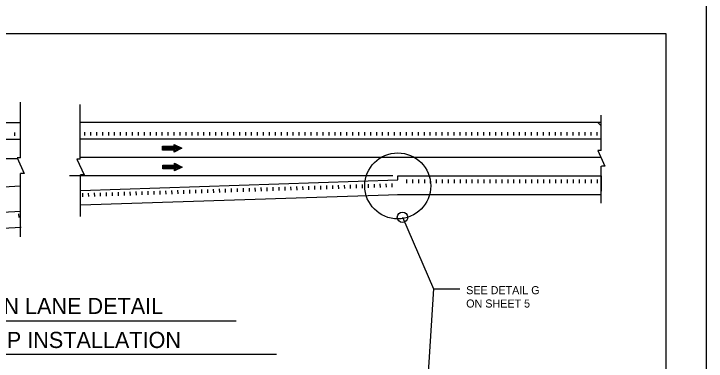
# Model space of a CAD drawing. Extents: x 632008 to 634206, y 294231 to 297795.
# Drawn here: x 632590.2 to 632848.9, y 295875.2 to 296005.1 of the extents above; entities that cross this region are included whole.
import ezdxf

# ---------------------------------------------------------------- set-up
doc = ezdxf.new("R2010")
doc.units = 0
for name, color, linetype in [('1', 7, 'Continuous'), ('2', 7, 'Continuous'), ('PLT-BNDY', 7, 'Continuous')]:
    doc.layers.add(name, color=color, linetype=linetype)

msp = doc.modelspace()

# ---------------------------------------------------------------- linework, layer by layer
at = {"layer": '1'}
for p, q in [((632590.51, 295960.77), (632590.51, 295959.44)), ((632616.63, 295960.88), (632616.63, 295959.54)), ((632618.85, 295960.88), (632618.85, 295959.54)), ((632621.08, 295960.88), (632621.08, 295959.54)), ((632623.3, 295960.88), (632623.3, 295959.54)), ((632625.53, 295960.88), (632625.53, 295959.54)), ((632627.75, 295960.88), (632627.75, 295959.54)), ((632629.98, 295960.88), (632629.98, 295959.54)), ((632632.2, 295960.88), (632632.2, 295959.54)), ((632634.43, 295960.88), (632634.43, 295959.54)), ((632636.65, 295960.88), (632636.65, 295959.54)), ((632638.88, 295960.88), (632638.88, 295959.54)), ((632641.1, 295960.88), (632641.1, 295959.54)), ((632643.33, 295960.88), (632643.33, 295959.54)), ((632645.55, 295960.88), (632645.55, 295959.54)), ((632647.78, 295960.88), (632647.78, 295959.54)), ((632650, 295960.88), (632650, 295959.54)), ((632652.23, 295960.88), (632652.23, 295959.54)), ((632654.45, 295960.88), (632654.45, 295959.54)), ((632656.68, 295960.88), (632656.68, 295959.54)), ((632658.9, 295960.88), (632658.9, 295959.54)), ((632661.13, 295960.88), (632661.13, 295959.54)), ((632663.35, 295960.88), (632663.35, 295959.54)), ((632665.58, 295960.88), (632665.58, 295959.54)), ((632667.8, 295960.88), (632667.8, 295959.54)), ((632670.03, 295960.88), (632670.03, 295959.54)), ((632672.25, 295960.88), (632672.25, 295959.54)), ((632674.48, 295960.88), (632674.48, 295959.54)), ((632676.7, 295960.88), (632676.7, 295959.54)), ((632678.93, 295960.88), (632678.93, 295959.54)), ((632681.15, 295960.88), (632681.15, 295959.54)), ((632683.38, 295960.88), (632683.38, 295959.54)), ((632685.6, 295960.88), (632685.6, 295959.54)), ((632687.83, 295960.88), (632687.83, 295959.54)), ((632690.05, 295960.88), (632690.05, 295959.54)), ((632692.28, 295960.88), (632692.28, 295959.54)), ((632694.5, 295960.88), (632694.5, 295959.54)), ((632696.73, 295960.88), (632696.73, 295959.54)), ((632698.95, 295960.88), (632698.95, 295959.54)), ((632701.18, 295960.88), (632701.18, 295959.54)), ((632703.4, 295960.88), (632703.4, 295959.54)), ((632705.63, 295960.88), (632705.63, 295959.54)), ((632707.85, 295960.88), (632707.85, 295959.54)), ((632710.08, 295960.88), (632710.08, 295959.54)), ((632712.3, 295960.88), (632712.3, 295959.54)), ((632714.53, 295960.88), (632714.53, 295959.54)), ((632716.75, 295960.88), (632716.75, 295959.54)), ((632718.98, 295960.88), (632718.98, 295959.54)), ((632721.2, 295960.88), (632721.2, 295959.54)), ((632723.43, 295960.88), (632723.43, 295959.54)), ((632725.65, 295960.88), (632725.65, 295959.54)), ((632727.88, 295960.88), (632727.88, 295959.54)), ((632730.1, 295960.88), (632730.1, 295959.54)), ((632732.33, 295960.88), (632732.33, 295959.54)), ((632734.55, 295960.88), (632734.55, 295959.54)), ((632736.78, 295960.88), (632736.78, 295959.54)), ((632739, 295960.88), (632739, 295959.54)), ((632741.23, 295960.88), (632741.23, 295959.54)), ((632743.45, 295960.88), (632743.45, 295959.54)), ((632745.68, 295960.88), (632745.68, 295959.54)), ((632747.9, 295960.88), (632747.9, 295959.54)), ((632750.13, 295960.88), (632750.13, 295959.54)), ((632752.35, 295960.88), (632752.35, 295959.54)), ((632754.58, 295960.88), (632754.58, 295959.54)), ((632756.8, 295960.88), (632756.8, 295959.54)), ((632759.02, 295960.88), (632759.02, 295959.54)), ((632761.25, 295960.88), (632761.25, 295959.54)), ((632763.48, 295960.88), (632763.48, 295959.54)), ((632765.7, 295960.88), (632765.7, 295959.54)), ((632767.93, 295960.88), (632767.93, 295959.54)), ((632770.15, 295960.88), (632770.15, 295959.54)), ((632772.38, 295960.88), (632772.38, 295959.54)), ((632774.6, 295960.88), (632774.6, 295959.54)), ((632776.83, 295960.88), (632776.83, 295959.54)), ((632779.05, 295960.88), (632779.05, 295959.54)), ((632781.27, 295960.88), (632781.27, 295959.54)), ((632783.5, 295960.88), (632783.5, 295959.54)), ((632785.73, 295960.88), (632785.73, 295959.54)), ((632787.95, 295960.88), (632787.95, 295959.54)), ((632790.17, 295960.88), (632790.17, 295959.54)), ((632792.4, 295960.88), (632792.4, 295959.54)), ((632794.62, 295960.88), (632794.62, 295959.54)), ((632796.85, 295960.88), (632796.85, 295959.54)), ((632799.08, 295960.88), (632799.08, 295959.54)), ((632801.3, 295960.88), (632801.3, 295959.54)), ((632803.52, 295960.88), (632803.52, 295959.54)), ((632805.75, 295960.88), (632805.75, 295959.54)), ((632807.98, 295960.88), (632807.98, 295959.54)), ((632616.43, 295944.89), (632615.17, 295944.89)), ((632716.04, 295939.81), (632716, 295941.15)), ((632718.27, 295939.88), (632718.23, 295941.22)), ((632720.49, 295939.95), (632720.45, 295941.29)), ((632722.72, 295940.02), (632722.68, 295941.36)), ((632724.94, 295940.09), (632724.9, 295941.43)), ((632727.16, 295940.16), (632727.12, 295941.5)), ((632729.39, 295940.24), (632729.35, 295941.57)), ((632731.61, 295940.31), (632731.57, 295941.64)), ((632737.04, 295941.82), (632737.04, 295943.16)), ((632739.26, 295941.82), (632739.26, 295943.16)), ((632741.48, 295941.82), (632741.48, 295943.16)), ((632743.71, 295941.82), (632743.71, 295943.16)), ((632745.93, 295941.82), (632745.93, 295943.16)), ((632748.15, 295941.82), (632748.15, 295943.16)), ((632750.38, 295941.82), (632750.38, 295943.16)), ((632752.6, 295941.82), (632752.6, 295943.16)), ((632754.82, 295941.82), (632754.82, 295943.16)), ((632757.05, 295941.82), (632757.05, 295943.16)), ((632759.27, 295941.82), (632759.27, 295943.16)), ((632761.49, 295941.82), (632761.49, 295943.16)), ((632763.72, 295941.82), (632763.72, 295943.16)), ((632765.94, 295941.82), (632765.94, 295943.16)), ((632768.17, 295941.82), (632768.17, 295943.16)), ((632770.39, 295941.82), (632770.39, 295943.16)), ((632772.61, 295941.82), (632772.61, 295943.16)), ((632774.84, 295941.82), (632774.84, 295943.16)), ((632777.06, 295941.82), (632777.06, 295943.16)), ((632779.29, 295941.82), (632779.29, 295943.16)), ((632781.52, 295941.82), (632781.52, 295943.16)), ((632783.74, 295941.82), (632783.74, 295943.16)), ((632785.96, 295941.82), (632785.96, 295943.16)), ((632788.19, 295941.82), (632788.19, 295943.16)), ((632790.42, 295941.82), (632790.42, 295943.16)), ((632792.64, 295941.82), (632792.64, 295943.16)), ((632794.86, 295941.82), (632794.86, 295943.16)), ((632797.09, 295941.82), (632797.09, 295943.16)), ((632799.31, 295941.82), (632799.31, 295943.16)), ((632801.54, 295941.82), (632801.54, 295943.16)), ((632803.77, 295941.82), (632803.77, 295943.16)), ((632805.99, 295941.82), (632805.99, 295943.16)), ((632808.21, 295941.82), (632808.21, 295943.16)), ((632633.76, 295937.21), (632633.72, 295938.54)), ((632635.98, 295937.28), (632635.94, 295938.61)), ((632638.21, 295937.35), (632638.17, 295938.68)), ((632640.43, 295937.42), (632640.39, 295938.75)), ((632642.66, 295937.49), (632642.62, 295938.82)), ((632644.88, 295937.56), (632644.84, 295938.89)), ((632647.1, 295937.63), (632647.06, 295938.96)), ((632649.33, 295937.7), (632649.29, 295939.03)), ((632651.55, 295937.77), (632651.51, 295939.11)), ((632653.78, 295937.84), (632653.74, 295939.18)), ((632656, 295937.91), (632655.96, 295939.25)), ((632658.22, 295937.98), (632658.18, 295939.32)), ((632660.45, 295938.05), (632660.41, 295939.39)), ((632662.67, 295938.12), (632662.63, 295939.46)), ((632664.9, 295938.19), (632664.85, 295939.53)), ((632667.12, 295938.26), (632667.08, 295939.6)), ((632669.34, 295938.33), (632669.3, 295939.67)), ((632671.57, 295938.4), (632671.53, 295939.74)), ((632673.79, 295938.48), (632673.75, 295939.81)), ((632676.02, 295938.55), (632675.97, 295939.88)), ((632678.24, 295938.62), (632678.2, 295939.95)), ((632680.46, 295938.69), (632680.42, 295940.02)), ((632682.69, 295938.76), (632682.64, 295940.09)), ((632684.91, 295938.83), (632684.87, 295940.16)), ((632687.13, 295938.9), (632687.09, 295940.23)), ((632689.36, 295938.97), (632689.32, 295940.3)), ((632691.58, 295939.04), (632691.54, 295940.37)), ((632693.81, 295939.11), (632693.76, 295940.44)), ((632696.03, 295939.18), (632695.99, 295940.51)), ((632698.25, 295939.25), (632698.21, 295940.58)), ((632700.48, 295939.32), (632700.44, 295940.65)), ((632702.7, 295939.39), (632702.66, 295940.72)), ((632704.92, 295939.46), (632704.88, 295940.79)), ((632707.15, 295939.53), (632707.11, 295940.87)), ((632709.37, 295939.6), (632709.33, 295940.94)), ((632711.6, 295939.67), (632711.56, 295941.01)), ((632713.82, 295939.74), (632713.78, 295941.08)), ((632615.97, 295936.65), (632615.93, 295937.98)), ((632618.19, 295936.72), (632618.15, 295938.05)), ((632620.42, 295936.79), (632620.38, 295938.12)), ((632622.64, 295936.86), (632622.6, 295938.19)), ((632624.87, 295936.93), (632624.82, 295938.26)), ((632627.09, 295937), (632627.05, 295938.33)), ((632629.31, 295937.07), (632629.27, 295938.4)), ((632631.54, 295937.14), (632631.5, 295938.47)), ((632592.15, 295928.91), (632592.06, 295930.3)), ((632735.41, 295928.99), (632747.02, 295902.24)), ((632747.02, 295902.24), (632743.17, 295844.09))]:
    msp.add_line(p, q, dxfattribs=at)
msp.add_lwpolyline([(632833.86, 295433.62), (632833.86, 295997.62), (632047.86, 295997.62), (632047.86, 295433.62), (632833.86, 295433.62), (632833.86, 295459.98), (632633.86, 295459.98), (632633.86, 295524.66), (632833.86, 295524.66), (632833.86, 295553.62), (632633.86, 295553.62), (632633.86, 295433.62), (632712.66, 295433.62), (632712.66, 295459.98), (632712.66, 295433.62), (632789.66, 295433.62), (632789.66, 295459.98), (632789.66, 295447.66), (632833.86, 295447.66)], dxfattribs=at)
msp.add_lwpolyline([(632833.86, 295433.62), (632833.86, 295997.62), (632047.86, 295997.62), (632047.86, 295433.62), (632833.86, 295433.62), (632833.86, 295459.98), (632633.86, 295459.98), (632633.86, 295524.66), (632833.86, 295524.66), (632833.86, 295553.62), (632633.86, 295553.62), (632633.86, 295433.62), (632712.66, 295433.62), (632712.66, 295459.98), (632712.66, 295433.62), (632789.66, 295433.62), (632789.66, 295459.98), (632789.66, 295447.66), (632833.86, 295447.66)], dxfattribs=at)
msp.add_lwpolyline([(632833.86, 295433.62), (632833.86, 295997.62), (632047.86, 295997.62), (632047.86, 295433.62), (632833.86, 295433.62), (632833.86, 295459.98), (632633.86, 295459.98), (632633.86, 295524.66), (632833.86, 295524.66), (632833.86, 295553.62), (632633.86, 295553.62), (632633.86, 295433.62), (632712.66, 295433.62), (632712.66, 295459.98), (632712.66, 295433.62), (632789.66, 295433.62), (632789.66, 295459.98), (632789.66, 295447.66), (632833.86, 295447.66)], dxfattribs=at)
msp.add_lwpolyline([(632833.86, 295433.62), (632833.86, 295997.62), (632047.86, 295997.62), (632047.86, 295433.62), (632833.86, 295433.62), (632833.86, 295459.98), (632633.86, 295459.98), (632633.86, 295524.66), (632833.86, 295524.66), (632833.86, 295553.62), (632633.86, 295553.62), (632633.86, 295433.62), (632712.66, 295433.62), (632712.66, 295459.98), (632712.66, 295433.62), (632789.66, 295433.62), (632789.66, 295459.98), (632789.66, 295447.66), (632833.86, 295447.66)], dxfattribs=at)
for centre, radius in [((632733.63, 295940.74), 12.32), ((632735.41, 295928.99), 1.94)]:
    msp.add_circle(centre, radius, dxfattribs=at)
at = {"layer": '2'}
for p, q in [((632592.68, 295951.26), (632592.68, 295972.03)), ((632615.01, 295950.72), (632615.01, 295971.21)), ((632809.6, 295953.93), (632809.6, 295967.25)), ((632375.3, 295964.48), (632592.68, 295964.48)), ((632615.01, 295964.58), (632809.6, 295964.58)), ((632592.68, 295958.13), (632375.3, 295958.13)), ((632809.6, 295958.24), (632615.01, 295958.24)), ((632808.33, 295953.93), (632811.03, 295948.1)), ((632809.6, 295953.93), (632808.33, 295953.93)), ((632591.57, 295950.93), (632375.3, 295950.93)), ((632591.41, 295951.26), (632594.11, 295945.42)), ((632592.68, 295951.26), (632591.41, 295951.26)), ((632613.74, 295950.72), (632616.43, 295944.89)), ((632615.01, 295950.72), (632613.74, 295950.72)), ((632809.52, 295951.35), (632615.01, 295951.35)), ((632809.6, 295934.3), (632809.6, 295948.1)), ((632811.03, 295948.1), (632809.76, 295948.1)), ((632594.11, 295945.42), (632592.68, 295945.42)), ((632592.68, 295921.72), (632592.68, 295945.42)), ((632731.8, 295944.46), (632610.98, 295944.46)), ((632615.17, 295929.34), (632615.17, 295944.89)), ((632733.7, 295943.01), (632733.7, 295944.46)), ((632733.7, 295944.46), (632809.6, 295944.46)), ((632809.6, 295944.46), (632809.6, 295938.72)), ((632809.6, 295944.46), (632809.6, 295938.72)), ((632615.17, 295939.06), (632733.7, 295943.01)), ((632615.17, 295933.62), (632734, 295937.58)), ((632733.55, 295937.57), (632809.6, 295937.57)), ((632747.02, 295902.24), (632756.86, 295902.24)), ((632526.57, 295890.29), (632673.28, 295890.29)), ((632510.77, 295877.77), (632688.38, 295877.77))]:
    msp.add_line(p, q, dxfattribs=at)
for points in [[(632808.22, 295964.58), (632809.5, 295963.3)], [(632645.8, 295955.57), (632650.1, 295955.57), (632650.1, 295956.29), (632652.98, 295954.85), (632650.1, 295953.42), (632650.1, 295954.14), (632645.8, 295954.14), (632645.8, 295955.57)], [(632645.94, 295955.43), (632645.8, 295955.57)], [(632645.94, 295955.43), (632650.25, 295955.43), (632650.25, 295956), (632652.54, 295954.85), (632650.25, 295953.71), (632650.25, 295954.28), (632645.94, 295954.28), (632645.94, 295955.29), (632650.54, 295955.29), (632650.39, 295955.72), (632651.97, 295954.85), (632650.39, 295953.99), (632650.54, 295954.57), (632646.23, 295954.57), (632646.23, 295955.14), (632650.82, 295955.14), (632651.4, 295954.85), (632650.82, 295954.57), (632650.82, 295954.85), (632646.38, 295954.85)], [(632645.88, 295948.51), (632650.18, 295948.51), (632650.18, 295949.23), (632653.05, 295947.79), (632650.18, 295946.36), (632650.18, 295947.07), (632645.88, 295947.07), (632645.88, 295948.51)], [(632646.02, 295948.36), (632650.32, 295948.36), (632650.32, 295948.94), (632652.62, 295947.79), (632650.32, 295946.64), (632650.32, 295947.22), (632646.02, 295947.22), (632646.02, 295948.22), (632650.61, 295948.22), (632650.47, 295948.65), (632652.05, 295947.79), (632650.47, 295946.93), (632650.61, 295947.5), (632646.31, 295947.5), (632646.31, 295948.08), (632650.9, 295948.08), (632651.47, 295947.79), (632650.9, 295947.5), (632650.9, 295947.79), (632646.45, 295947.79)], [(632646.02, 295948.36), (632645.88, 295948.51)]]:
    msp.add_lwpolyline(points, dxfattribs=at)
for centre, radius, start, end in [((632774.98, 292702.64), 3243.17, 93.22216, 93.52385), ((632700.4, 293979.01), 1955.11, 93.15336, 99.57394), ((632700.4, 293979.01), 1949.11, 93.15999, 99.59978)]:
    msp.add_arc(centre, radius, start, end, dxfattribs=at)
at = {"layer": 'PLT-BNDY'}
msp.add_lwpolyline([(632007.86, 296012.62), (632848.86, 296012.62), (632848.86, 295418.62), (632007.86, 295418.62)], close=True, dxfattribs=at)

# ---------------------------------------------------------------- texts
at = {"layer": '1'}
for s, height, p in [('SEE DETAIL G', 3, (632759.21, 295900.24)), ('ACCELERATION LANE DETAIL', 6.0395, (632529.32, 295892.82)), ('ON SHEET 5', 3, (632759.21, 295895.24)), ('FOR RUMBLE STRIP INSTALLATION', 6.0395, (632513.99, 295880.1))]:
    msp.add_text(s, height=height, dxfattribs=at).set_placement(p)

doc.saveas('drawing.dxf')
